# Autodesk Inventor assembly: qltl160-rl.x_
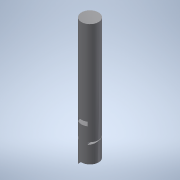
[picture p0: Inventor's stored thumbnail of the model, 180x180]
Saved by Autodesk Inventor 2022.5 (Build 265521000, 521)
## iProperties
Part Number: qltl160-rl.x_
Material: 一般
Document SubType Name: Assembly
Designer: ImaoCorp
Sending System: SOLIDWORKS 2017-2017317
MC: AMD64
MC_MODEL: Intel64 Family 6 Model 60 Stepping 3, GenuineIntel
OS: Windows_NT
FRU: Parasolid Version 29.0, build 201,  4-17-2017
FORMAT: text
GUISE: transmit
KEY: qltl160-rl
FILE: qltl160-rl.x_t
DATE: Wed Sep 04 15:35:48 2019
Author: ImaoCorp
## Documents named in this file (3)
- X:\14_SW2022-Inv2022\00_全2023-1023新製品(TCC)まで\q\qltl160-rl\QLTL160-RL.iam
- X:\14_SW2022-Inv2022\00_全2023-1023新製品(TCC)まで\q\qltl160-rl\qltl160-rl_01.ipt
- X:\14_SW2022-Inv2022\00_全2023-1023新製品(TCC)まで\q\qltl160-rl\qltl160-rl_02.ipt
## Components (2 placed, 2 different names)
1. qltl160-rl_01
2. qltl160-rl_02
